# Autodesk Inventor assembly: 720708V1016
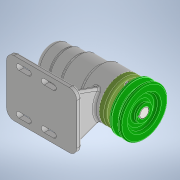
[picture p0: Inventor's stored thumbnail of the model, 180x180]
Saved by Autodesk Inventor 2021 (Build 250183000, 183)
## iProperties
Created: 2022-07
Part Number: 720708V1016
Document SubType Name: Assembly
Designer: owner
Author: owner
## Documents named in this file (12)
- C:\Users\owner\Desktop\720708V1016\720708V1016.iam
- C:\Users\owner\Desktop\720708V1016\본체.ipt
- C:\Users\owner\Desktop\720708V1016\V벨트풀리.ipt
- C:\Users\owner\Desktop\720708V1016\멈춤나사 M3.ipt
- C:\Users\owner\Desktop\720708V1016\베어링 6004.ipt
- C:\Users\owner\Desktop\720708V1016\베어링 51202.ipt
- C:\Users\owner\Desktop\720708V1016\볼트 M4.ipt
- C:\Users\owner\Desktop\720708V1016\어댑터슬리브.ipt
- C:\Users\owner\Desktop\720708V1016\오일 실 20x35x7.ipt
- C:\Users\owner\Desktop\720708V1016\축.ipt
- C:\Users\owner\Desktop\720708V1016\커버.ipt
- C:\Users\owner\Desktop\720708V1016\키 5x5.ipt
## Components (1 placed, 1 different names)
1. V벨트풀리:1
